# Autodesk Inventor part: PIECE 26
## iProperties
Created: 2004-11
Part Number: PIECE 26
Document SubType Name: Modeling
Designer: Bruno
Manufacturer: Standard
Standards Organization: Custom
Author: Bruno
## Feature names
1. Base1
